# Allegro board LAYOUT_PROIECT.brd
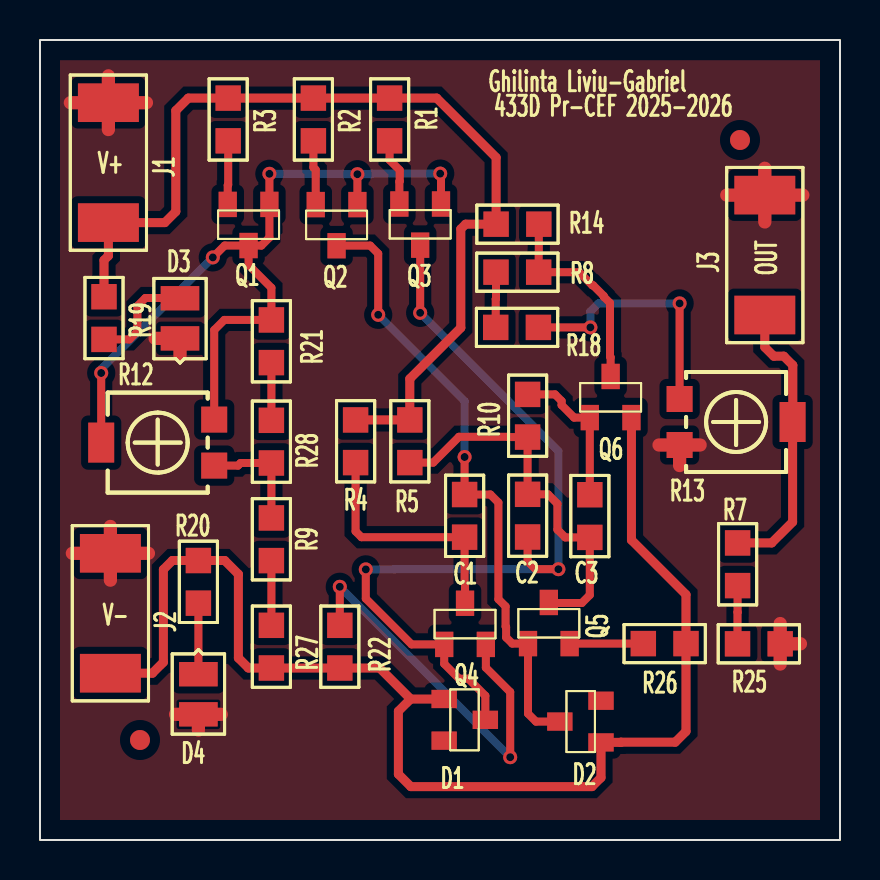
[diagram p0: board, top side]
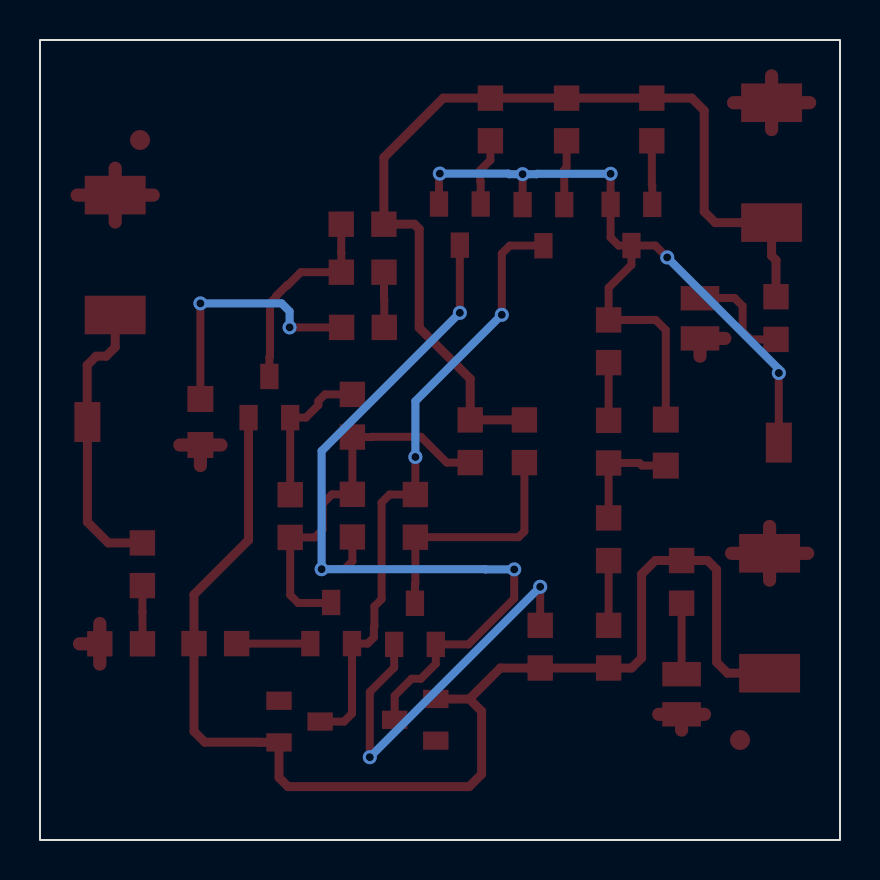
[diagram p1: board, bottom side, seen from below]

Outline 40 x 40 mm; copper layers: TOP, BOTTOM. Coordinates in mm from the lower left corner of the outline.
Outline path: rectangle 0,0 40,40

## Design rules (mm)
nets with their own width: min track width 0.4; nets N103383 N103451 N103463 N103557 N103581 N103587 N103701 N103715 N103835 N103897 N103911 N103917 N104055 N104249 N104493 N105640 N1034391 N1036391 N1041651 N1042051
nets with their own width: min track width 0.45; nets OUT+ V2- V+
nets with their own width: min track width 0.66; nets GND

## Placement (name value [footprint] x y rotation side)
C1  2.2n  [SMC0805]  21.23 15.14 90 top
C2  2.2n  [SMC0805]  24.38 15.15 90 top
C3  100p  [SMC0805]  27.49 15.13 90 top
D1  BZX84-C5V6  [TO236AA]  20.21 7.05 180 top
D2  BZX84-C5V6  [TO236AA]  28.05 4.88 0 top
D3  5V,LED,LED  [SMD0805]  7 25.08 90 top
D4  5V,LED,LED  [SMD0805]  7.92 8.29 270 top
J1  CON2  [SMR2512]  3.42 30.87 90 top
J2  CON2  [SMR2512]  3.52 8.34 90 top
J3  CON2  [SMR2512]  36.24 26.25 90 top
NOREF  -  [unnamed]  5 5 0 top
NOREF#2  -  [#2]  40 0 90 top
NOREF#3  -  [unnamed]  35 35 0 top
NOREF#4  -  [#2]  0 40 0 top
Q1  QBC856B  [TO236AA]  11.47 31.78 90 top
Q2  QBC856B  [TO236AA]  15.87 31.77 90 top
Q3  QBC856B  [TO236AA]  20.05 31.8 90 top
Q4  QBC846B  [TO236AA]  20.21 9.78 270 top
Q5  QBC846B  [TO236AA]  24.4 9.82 270 top
Q6  QBC846B  [TO236AA]  27.49 21.12 270 top
R1  2k  [SMR0805]  17.48 34.96 90 top
R2  2k  [SMR0805]  13.67 34.96 90 top
R3  1.5k  [SMR0805]  9.41 34.96 90 top
R4  2k  [SMR0805]  15.78 18.87 90 top
R5  2k  [SMR0805]  18.49 18.87 90 top
R7  15k  [SMR0805]  34.88 12.72 90 top
R8  9.1k  [SMR0805]  22.8 28.39 0 top
R9  15k  [SMR0805]  11.57 13.97 90 top
R10  10k  [SMR0805]  24.38 22.28 270 top
R12  500k  [TS53YL]  8.71 21.02 0 top
R13  10K  [TS53YL]  31.98 19.75 180 top
R14  2k  [SMR0805]  24.94 30.79 180 top
R18  10k  [SMR0805]  24.92 25.63 180 top
R19  220  [SMR0805]  3.2 25.03 90 top
R20  220  [SMR0805]  7.92 11.84 90 top
R21  150k  [SMR0805]  11.57 23.87 90 top
R22  33  [SMR0805]  14.99 8.6 90 top
R25  1k  [SMR0805]  37.01 9.81 180 top
R26  33  [SMR0805]  32.3 9.82 180 top
R27  2.7k  [SMR0805]  11.57 8.6 90 top
R28  10k  [SMR0805]  11.57 18.85 90 top

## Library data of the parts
C1-C3 = C
D1 D2 = BZX84-C5V6_9
D3 D4 = LED_5
J1-J3 = CON2
Q1-Q3 = QBC856B_0
Q4-Q6 = QBC846B_0
R1-R5 R7-R10 R14 R18-R22 R25-R28 = R
R12 R13 = POT_0

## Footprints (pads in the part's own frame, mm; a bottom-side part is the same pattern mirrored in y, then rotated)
SMC0805
  rect 1.27x1.27 smd: 1(0,0) 2(2.134,0)
SMD0805
  rect 1.219x1.93 smd: A(2.007,0) C(0,0)
SMR0805
  rect 1.27x1.27 smd: 1(0,0) 2(2.134,0)
SMR2512
  rect 1.93x3.048 smd: 1(0,0) 2(5.994,0)
TO236AA
  rect 1.27x0.914 smd: 1(0,0) 2(0,2.083) 3(-2.057,1.041)
TS53YL
  rect 1.3x1.3 smd: 1(0,0) 3(0,-2.3)
  rect 1.3x2 smd: 2(-5.65,-1.15)
unnamed
  round 1 smd: (0,0)

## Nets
GND: D3.C D4.A J1.2 J2.2 J3.2 R13.1 R25.1
V2-: D1.1 D2.1 J2.1 Q6.2(E) R20.2 R22.1 R26.1 R27.1
OUT+: J3.1 R7.2 R13.2(WIPER)
V+: J1.1 R1.2 R2.2 R3.2 R4.2 R5.2 R14.2 R19.2
N103383: D3.A R19.1
N103451: Q3.2(E) R1.1
N103463: Q2.2(E) R2.1
N103557: Q1.1 Q1.3 Q2.1 Q3.1 R12.1 R12.2(WIPER) R21.2
N103581: C1.2 D2.3(C) Q2.3 Q5.1
N103587: C2.1 D1.3(C) Q3.3 Q4.1
N103701: Q6.3 R8.2 R14.1
N103715: R13.3 R18.1
N103835: R21.1 R28.2
N103897: C2.2 C3.1 Q5.3 R5.1 R10.2
N103911: R9.2 R12.3 R28.1
N103917: C1.1 Q4.3 R4.1
N104055: C3.2 Q6.1 R10.1
N104249: R7.1 R25.2
N104493: D4.C R20.1
N105640: Q4.2(E) R22.2
N1034391: Q1.2(E) R3.1
N1036391: R8.1 R18.2
N1041651: Q5.2(E) R26.2
N1042051: R9.1 R27.2

Pads without a net: D1 2; D2 2

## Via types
v1: diameter 0.7, hole 0.4, TOP to BOTTOM, 14 vias

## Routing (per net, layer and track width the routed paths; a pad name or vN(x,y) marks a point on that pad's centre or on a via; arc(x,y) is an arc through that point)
GND: length 30.8
  TOP w0.66: J3.2 38.14,32.24 ; J3.2 36.24,30.9 ; J3.2 36.24,33.59 ; J3.2 34.34,32.24 ; 7,24.19 D3.C 5.76,25.08 ; 1.62,14.33 J2.2 ; J2.2 3.52,12.99 ; J2.2 3.52,15.68 ; J2.2 5.42,14.33 ; 6.78,6.28 D4.A ; D4.A 7.92,5.5 ; D4.A 9.06,6.28 ; R13.1 33.01,19.75 ; R13.1 30.95,19.75 ; R13.1 31.98,18.72 ; R25.1 38.02,9.81 ; R25.1 37.01,10.82 ; R25.1 37.01,8.8 ; 3.42,35.52 J1.2 ; J1.2 1.52,36.86 ; J1.2 3.42,38.21 ; J1.2 5.32,36.86
V2-: length 64.7
  TOP w0.45: Q6.2 29.57,15 32.3,12.27 R26.1 32.3,5.43 31.76,4.89 29.05,4.89 29.04,4.88 D2.1 28.05,3.12 27.6,2.67 18.54,2.67 17.92,3.29 17.92,6.44 18.53,7.05 ; 18.53,7.05 16.98,8.6 R22.1 R27.1 10.42,8.6 9.92,9.1 9.92,13.29 9.24,13.97 R20.2 6.62,13.97 6.17,13.52 6.17,8.89 5.62,8.34 J2.1 ; 18.53,7.05 D1.1
OUT+: length 14.4
  TOP w0.45: J3.1 36.24,24.64 36.69,24.19 37.19,24.19 37.64,23.74 37.64,20.91 R13.2 37.63,15.9 36.58,14.85 R7.2
V+: length 48.5
  TOP w0.45: R19.2 3.2,28.99 3.42,29.21 J1.1 6.24,30.87 6.79,31.42 6.79,36.47 7.41,37.09 R3.2 R2.2 R1.2 19.84,37.09 22.81,34.12 R14.2 21.28,30.79 21.04,30.55 21.04,25.61 18.49,23.06 R5.2 R4.2
N103383: length 5.4
  TOP w0.4: D3.A 6.99,27.1 5.27,27.1 4.87,26.7 4.87,25.43 4.47,25.03 R19.1
N103451: length 3.4
  TOP w0.4: R1.1 17.48,34 17.99,33.49 17.99,32.94 17.97,32.92 Q3.2
N103463: length 3.2
  TOP w0.4: Q2.2 13.79,33.51 13.67,33.63 R2.1
N103557: length 41.4
  TOP w0.4: Q3.1 20.05,33.28 v1(20.01,33.32) ; v1(15.87,33.29) Q2.1 ; v1(11.47,33.31) Q1.1 11.47,30.12 11.07,29.72 Q1.3 ; v1(8.64,29.13) 9.23,29.72 Q1.3 ; Q1.3 10.43,28.75 11.57,27.61 R21.2 9.22,26 8.71,25.5 R12.1 ; v1(3.06,23.35) R12.2
  BOTTOM w0.4: v1(8.64,29.13) 3.06,23.55 v1(3.06,23.35) ; v1(11.47,33.31) 15.15,33.31 15.17,33.29 v1(15.87,33.29) 16.55,33.29 16.58,33.32 v1(20.01,33.32)
N103581: length 31.3
  TOP w0.4: Q2.3 14.84,29.72 16.51,29.72 16.91,29.32 v1(16.91,26.26) ; v1(21.23,19.15) C1.2 22.52,17.27 22.92,16.87 22.92,12.04 23.28,11.68 23.28,10.67 23.3,10.64 23.3,10.13 23.62,9.82 Q5.1 24.4,6.32 24.8,5.92 25.99,5.92 D2.3
  BOTTOM w0.4: v1(21.23,19.15) 21.23,21.94 v1(16.91,26.26)
N103587: length 42.8
  TOP w0.4: v1(16.29,13.53) 16.29,12.07 18.58,9.78 Q4.1 20.21,8.81 20.96,8.06 21.42,8.06 22.27,7.21 D1.3 ; Q3.3 v1(19.01,26.36) ; v1(25.92,13.54) 24.78,13.54 24.38,13.94 C2.1
  BOTTOM w0.4: v1(19.01,26.36) 25.92,19.45 v1(25.92,13.54) 17.73,13.54 17.72,13.53 v1(16.29,13.53)
N103701: length 10.3
  TOP w0.4: Q6.3 28.53,24.14 28.5,24.17 28.5,26.85 28.18,27.16 28.18,27.2 27.65,27.73 27.61,27.73 26.96,28.39 R8.2 24.93,29.35 24.94,29.36 R14.1
N103715: length 12.8
  TOP w0.4: v1(31.98,26.83) R13.3 ; R18.1 v1(27.52,25.63)
  BOTTOM w0.4: v1(31.98,26.83) 27.92,26.83 27.52,26.43 v1(27.52,25.63)
N103835: length 2.9
  TOP w0.4: R21.1 R28.2
N103897: length 19.2
  TOP w0.4: R5.1 19.66,18.87 20.95,20.16 23.4,20.16 23.42,20.15 R10.2 C2.2 25.4,17.28 25.87,16.81 25.87,15.52 26.26,15.13 C3.1 27.49,12.25 27.09,11.85 25.47,11.85 Q5.3
N103911: length 5.7
  TOP w0.4: R9.2 R28.1 10.03,18.85 9.9,18.72 R12.3
N103917: length 12.3
  TOP w0.4: Q4.3 21.25,12.8 21.23,12.82 C1.1 16.07,15.14 15.78,15.43 R4.1
N104055: length 7.6
  TOP w0.4: R10.1 25.75,22.28 26.08,21.95 26.08,21.75 26.71,21.12 Q6.1 C3.2
N104249: length 2.9
  TOP w0.4: R7.1 34.88,11.39 34.88,11.39 R25.2
N104493: length 3.6
  TOP w0.4: R20.1 D4.C
N105640: length 20.1
  TOP w0.4: v1(23.51,4.14) 23.51,7.4 22.29,8.62 Q4.2 ; R22.2 v1(14.99,12.66)
  BOTTOM w0.4: v1(23.51,4.14) v1(14.99,12.66)
N1034391: length 3.2
  TOP w0.4: Q1.2 9.39,32.74 9.41,32.76 R3.1
N1036391: length 2.8
  TOP w0.4: R18.2 22.79,27.05 22.8,27.06 R8.1
N1041651: length 3.7
  TOP w0.4: Q5.2 R26.2
N1042051: length 3.2
  TOP w0.4: R9.1 R27.2

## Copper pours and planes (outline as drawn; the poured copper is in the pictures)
GND on TOP: 1,1 1,38.99 39,38.99 39,1 ; 10 cut-outs

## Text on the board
Ref Des/Silkscreen Top: V+ | V- | Ghilinta Liviu-Gabriel | 433D Pr-CEF 2025-2026 | OUT
MECANIC: *  SURFACE | L1 TOP CONDUCTOR | *  DIELECTRIC | L2 BOTTOM CONDUCTOR | DESIGN CROSS SECTION CHART | ___________________________ | TOTAL THICKNESS 1.6 MM | 1-2 | FIGURE | FINISHED_SIZE | 0.4 | DRILL CHART: TOP to BOTTOM | ALL UNITS ARE IN MILLIMETERS | PLATED | QTY | 15 | TOTAL HOLES:
